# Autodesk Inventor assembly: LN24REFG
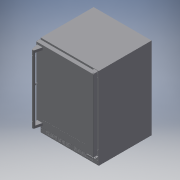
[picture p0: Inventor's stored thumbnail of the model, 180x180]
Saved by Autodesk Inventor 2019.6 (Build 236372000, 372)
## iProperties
Company: none
Created: 2025-04
Part Number: LN24REFG
Description: CATIA V5 STEP
Document SubType Name: Assembly
Designer: MMAK
Authority: none
Title: C:\Users\MMAK\Documents\SmarTeam\WEBSITE CAD\Lynx STP\LN24REFG.stp
Author: none
Sending System: CATIA V5 STEP AP203 v2
Preprocessor: CATIA Unofficial Packaging Version SP2
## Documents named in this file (4)
- C:\Users\MMAK\Documents\SmarTeam\WEBSITE CAD\Lynx STP\LN24REFG.iam
- C:\Users\MMAK\Documents\SmarTeam\WEBSITE CAD\Lynx STP\VORE224-SS41A.iam
- C:\Users\MMAK\Documents\SmarTeam\WEBSITE CAD\Lynx STP\OC UC 24.ipt
- C:\Users\MMAK\Documents\SmarTeam\WEBSITE CAD\Lynx STP\Product90.iam
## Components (3 placed, 3 different names)
1. VORE224-SS41A.1 [sub-assembly]
2. OC UC 24.1
3. Product90.2 [sub-assembly]
